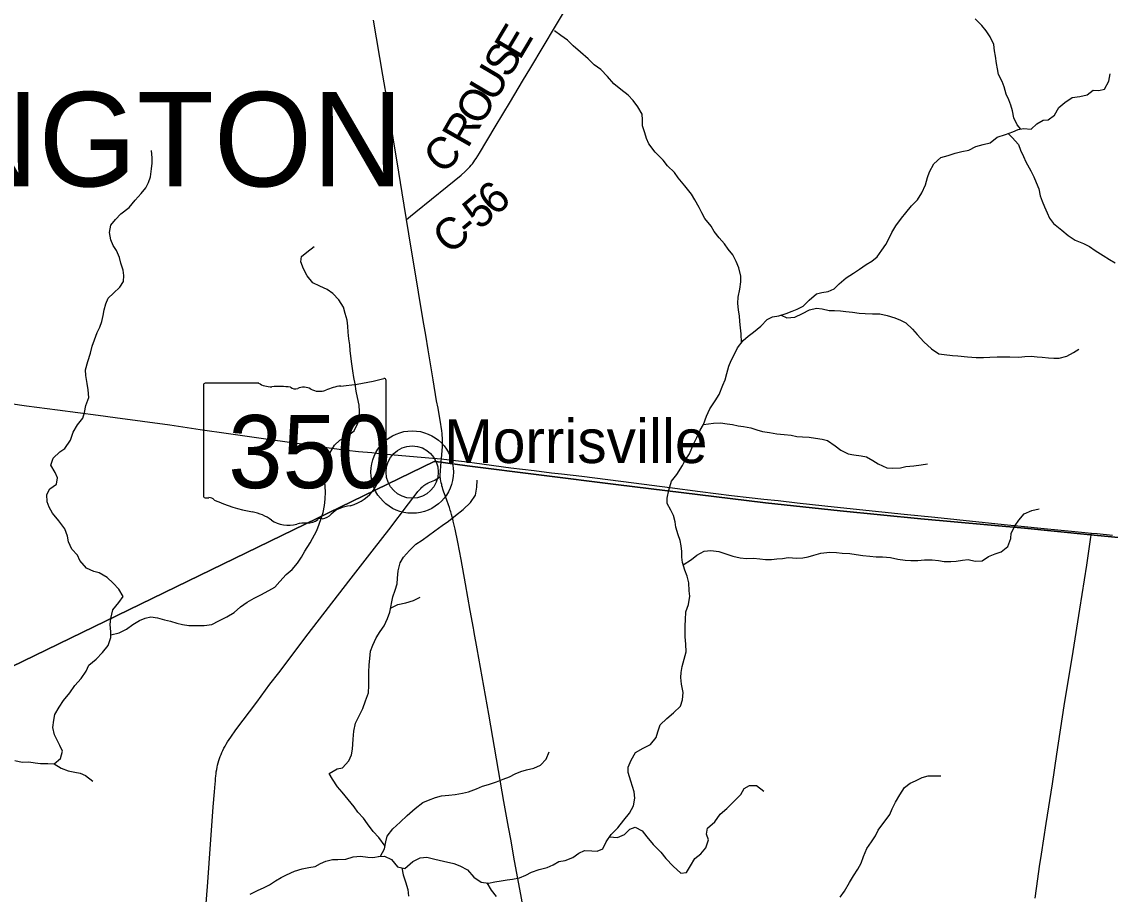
# Model space of a CAD drawing. Extents: x 1442749 to 1756758, y 235267 to 677782.
# Drawn here: x 1596416 to 1606786, y 492250 to 500562 of the extents above; entities that cross this region are included whole.
import ezdxf

# ---------------------------------------------------------------- set-up
doc = ezdxf.new("R2010")
doc.units = 0
for name, color, linetype in [('GM_X_County_Road', 7, 'Continuous'), ('GM_X_County_Road_Text', 7, 'Continuous'), ('GM_X_Minor_River', 7, 'Continuous'), ('GM_X_State_Location', 7, 'Continuous'), ('GM_X_State_Route', 7, 'Continuous'), ('GM_X_State_Shield', 7, 'Continuous'), ('GM_X_Township', 7, 'Continuous'), ('GM_X_Township_Road', 7, 'Continuous'), ('GM_X_Township_Text', 7, 'Continuous'), ('GM_X_Unincorporated', 7, 'Continuous'), ('GM_X_Unincorporated_Location', 7, 'Continuous'), ('GM_X_Unincorporated_Text', 7, 'Continuous')]:
    doc.layers.add(name, color=color, linetype=linetype)

msp = doc.modelspace()

# ---------------------------------------------------------------- linework, layer by layer
at = {"layer": 'GM_X_County_Road'}
for points in [[(1600081, 498678), (1600119, 498709), (1600170, 498750), (1600468, 498992), (1600603, 499102), (1600640, 499134), (1600655, 499149), (1600670, 499163), (1600684, 499179), (1600698, 499195), (1600710, 499210), (1600722, 499226), (1600734, 499242), (1600745, 499258), (1600761, 499284), (1600778, 499310), (1600928, 499560), (1601073, 499803), (1601188, 499997), (1601265, 500127), (1601501, 500521), (1601651, 500772)], [(1598161, 492001), (1598189, 492364), (1598201, 492547), (1598240, 493083), (1598253, 493227), (1598259, 493302), (1598261, 493326), (1598263, 493353), (1598265, 493377), (1598267, 493396), (1598270, 493416), (1598274, 493438), (1598278, 493461), (1598282, 493481), (1598288, 493502), (1598295, 493524), (1598300, 493543), (1598307, 493561), (1598315, 493582), (1598323, 493601), (1598332, 493621), (1598343, 493641), (1598353, 493661), (1598365, 493680), (1598377, 493701), (1598393, 493726), (1598408, 493747), (1598457, 493816), (1598656, 494081), (1598781, 494250), (1598864, 494360), (1599146, 494730), (1599532, 495232), (1599778, 495548), (1599912, 495722), (1600101, 495970), (1600182, 496077), (1600191, 496087), (1600206, 496104), (1600217, 496116), (1600229, 496127), (1600238, 496135), (1600248, 496143), (1600258, 496150), (1600267, 496156), (1600278, 496163), (1600289, 496169), (1600351, 496196), (1600366, 496203), (1600378, 496211), (1600404, 496229)]]:
    msp.add_lwpolyline(points, dxfattribs=at)
at = {"layer": 'GM_X_Minor_River'}
for points in [[(1605936, 499540), (1605900, 499579), (1605869, 499646), (1605856, 499712), (1605839, 499767), (1605821, 499817), (1605796, 499871), (1605775, 499942), (1605756, 499992), (1605722, 500059), (1605711, 500113), (1605704, 500165), (1605693, 500233), (1605685, 500284), (1605676, 500344), (1605643, 500418), (1605604, 500475), (1605562, 500526), (1605499, 500591)], [(1603274, 497506), (1603271, 497589), (1603265, 497645), (1603258, 497708), (1603255, 497760), (1603245, 497814), (1603238, 497882), (1603241, 497938), (1603256, 498014), (1603267, 498084), (1603266, 498138), (1603247, 498217), (1603224, 498279), (1603192, 498342), (1603145, 498394), (1603112, 498447), (1603062, 498502), (1603013, 498564), (1602986, 498615), (1602924, 498688), (1602895, 498742), (1602870, 498793), (1602830, 498864), (1602797, 498918), (1602732, 498999), (1602669, 499074), (1602635, 499127), (1602568, 499190), (1602527, 499242), (1602452, 499319), (1602392, 499398), (1602369, 499449), (1602354, 499503), (1602331, 499571), (1602329, 499628), (1602328, 499680), (1602285, 499752), (1602242, 499811), (1602194, 499862), (1602123, 499915), (1602057, 499970), (1601996, 500041), (1601933, 500106), (1601871, 500153), (1601812, 500210), (1601738, 500273), (1601669, 500332), (1601616, 500386), (1601552, 500431), (1601492, 500476)], [(1603097, 497100), (1603118, 497152), (1603135, 497212), (1603154, 497282), (1603175, 497334), (1603210, 497403), (1603235, 497455), (1603288, 497525), (1603338, 497566), (1603389, 497606), (1603458, 497661), (1603517, 497726), (1603570, 497750), (1603630, 497759), (1603698, 497784), (1603755, 497805), (1603805, 497825), (1603860, 497852), (1603917, 497909), (1603988, 497969), (1604038, 497982), (1604098, 497991), (1604155, 498019), (1604205, 498066), (1604270, 498123), (1604339, 498166), (1604398, 498206), (1604461, 498251), (1604515, 498282), (1604566, 498322), (1604609, 498387), (1604650, 498439), (1604677, 498493), (1604705, 498553), (1604744, 498618), (1604797, 498690), (1604838, 498741), (1604893, 498807), (1604950, 498866), (1604993, 498932), (1605026, 499007), (1605045, 499077), (1605064, 499131), (1605107, 499207), (1605172, 499270), (1605241, 499287), (1605309, 499310), (1605374, 499326), (1605438, 499339), (1605507, 499374), (1605577, 499391), (1605643, 499410), (1605710, 499462), (1605789, 499487), (1605857, 499512), (1605910, 499535), (1605960, 499544), (1606034, 499540), (1606087, 499589), (1606146, 499624), (1606196, 499626), (1606255, 499671), (1606298, 499745), (1606353, 499792), (1606423, 499841), (1606496, 499850), (1606566, 499867), (1606625, 499909), (1606677, 499906), (1606731, 499921), (1606774, 499997), (1606787, 500065)], [(1605813, 499496), (1605853, 499460), (1605912, 499391), (1605931, 499338), (1605961, 499278), (1605982, 499228), (1606029, 499143), (1606058, 499086), (1606082, 499032), (1606105, 498971), (1606118, 498905), (1606137, 498853), (1606159, 498800), (1606186, 498742), (1606207, 498691), (1606247, 498641), (1606324, 498578), (1606384, 498525), (1606451, 498482), (1606533, 498449), (1606589, 498420), (1606644, 498383), (1606718, 498334), (1606778, 498297), (1606833, 498266)], [(1596771, 495807), (1596710, 495880), (1596678, 495937), (1596659, 495989), (1596654, 496059), (1596683, 496111), (1596746, 496158), (1596756, 496218), (1596735, 496269), (1596692, 496338), (1596715, 496405), (1596778, 496465), (1596828, 496496), (1596882, 496576), (1596905, 496653), (1596948, 496723), (1596997, 496787), (1597013, 496838), (1597026, 496906), (1597054, 496982), (1597050, 497054), (1597039, 497115), (1597026, 497191), (1597025, 497245), (1597046, 497325), (1597071, 497405), (1597088, 497471), (1597109, 497533), (1597134, 497601), (1597159, 497654), (1597180, 497706), (1597192, 497764), (1597203, 497818), (1597218, 497874), (1597239, 497930), (1597289, 497975), (1597352, 498035), (1597387, 498088), (1597388, 498146), (1597383, 498197), (1597360, 498261), (1597346, 498315), (1597319, 498382), (1597288, 498432), (1597264, 498485), (1597251, 498555), (1597264, 498623), (1597309, 498679), (1597360, 498732), (1597439, 498793), (1597496, 498861), (1597555, 498926), (1597598, 498979), (1597625, 499031), (1597643, 499083), (1597654, 499161), (1597659, 499215), (1597658, 499265), (1597653, 499334)], [(1597266, 494721), (1597344, 494740), (1597413, 494775), (1597476, 494820), (1597538, 494859), (1597593, 494881), (1597645, 494892), (1597711, 494883), (1597777, 494864), (1597835, 494852), (1597893, 494833), (1597949, 494820), (1598009, 494809), (1598079, 494810), (1598153, 494811), (1598226, 494820), (1598294, 494854), (1598371, 494893), (1598440, 494934), (1598499, 494989), (1598563, 495033), (1598632, 495070), (1598695, 495103), (1598771, 495144), (1598826, 495177), (1598875, 495229), (1598934, 495296), (1598993, 495344), (1599042, 495403), (1599083, 495461), (1599113, 495520), (1599165, 495598), (1599226, 495717), (1599249, 495777), (1599268, 495829), (1599287, 495887), (1599302, 495953), (1599307, 496013), (1599310, 496083), (1599308, 496133), (1599303, 496183), (1599304, 496244), (1599306, 496296), (1599323, 496372), (1599351, 496453), (1599396, 496529), (1599447, 496576), (1599519, 496616), (1599582, 496665), (1599617, 496739), (1599630, 496794), (1599635, 496849), (1599630, 496909), (1599614, 496981), (1599601, 497043), (1599592, 497112), (1599581, 497172), (1599570, 497236), (1599561, 497302), (1599552, 497375), (1599546, 497429), (1599541, 497485), (1599534, 497541), (1599525, 497604), (1599523, 497662), (1599518, 497720), (1599499, 497784), (1599482, 497843), (1599438, 497913), (1599381, 497972), (1599325, 498011), (1599256, 498044), (1599190, 498075), (1599135, 498140), (1599102, 498208), (1599074, 498275), (1599081, 498325), (1599132, 498366), (1599201, 498422)], [(1603651, 497766), (1603706, 497742), (1603780, 497747), (1603853, 497782), (1603921, 497817), (1603988, 497832), (1604042, 497828), (1604108, 497811), (1604160, 497810), (1604218, 497807), (1604268, 497801), (1604330, 497796), (1604396, 497785), (1604452, 497784), (1604521, 497781), (1604591, 497778), (1604661, 497763), (1604733, 497740), (1604788, 497718), (1604840, 497693), (1604904, 497634), (1604947, 497583), (1605012, 497512), (1605084, 497447), (1605155, 497400), (1605205, 497392), (1605283, 497383), (1605333, 497380), (1605427, 497369), (1605508, 497362), (1605578, 497363), (1605638, 497366), (1605708, 497371), (1605831, 497369), (1605915, 497366), (1605973, 497372), (1606033, 497375), (1606089, 497370), (1606139, 497367), (1606197, 497361), (1606250, 497358), (1606300, 497357), (1606372, 497375), (1606435, 497410), (1606487, 497443)], [(1599812, 492609), (1599873, 492612), (1599938, 492581), (1599996, 492513), (1600065, 492496), (1600141, 492561), (1600213, 492596), (1600276, 492605), (1600353, 492586), (1600435, 492567), (1600533, 492544), (1600591, 492521), (1600663, 492484), (1600722, 492413), (1600794, 492366), (1600862, 492357), (1600922, 492370), (1600984, 492378), (1601041, 492387), (1601093, 492394), (1601159, 492407), (1601220, 492433), (1601272, 492460), (1601345, 492485), (1601421, 492504), (1601478, 492531), (1601534, 492563), (1601595, 492572), (1601665, 492601), (1601724, 492643), (1601778, 492666), (1601847, 492665), (1601897, 492662), (1601953, 492682), (1601984, 492751), (1602033, 492819), (1602094, 492882), (1602151, 492956), (1602206, 493023), (1602245, 493093), (1602258, 493167), (1602251, 493227), (1602220, 493328), (1602194, 493410), (1602194, 493462), (1602221, 493528), (1602262, 493600), (1602335, 493641), (1602406, 493678), (1602459, 493745), (1602477, 493799), (1602498, 493865), (1602561, 493924), (1602626, 493980), (1602691, 494043), (1602712, 494101), (1602719, 494171), (1602702, 494251), (1602695, 494314), (1602700, 494364), (1602708, 494420), (1602727, 494491), (1602746, 494561), (1602743, 494634), (1602738, 494704), (1602736, 494812), (1602741, 494866), (1602742, 494940), (1602769, 495010), (1602780, 495090), (1602776, 495142), (1602773, 495216), (1602756, 495281), (1602735, 495337), (1602710, 495412), (1602704, 495462), (1602705, 495514), (1602698, 495568), (1602689, 495620), (1602669, 495673), (1602648, 495747), (1602641, 495797), (1602624, 495858), (1602600, 495908), (1602565, 495973), (1602566, 496023), (1602581, 496101), (1602606, 496185), (1602657, 496250), (1602710, 496334), (1602737, 496385), (1602778, 496447), (1602817, 496537), (1602848, 496602), (1602881, 496672), (1602910, 496724), (1602941, 496804), (1602972, 496875), (1603021, 496951), (1603060, 497011), (1603097, 497100)], [(1602910, 496724), (1603006, 496737), (1603073, 496740), (1603137, 496733), (1603187, 496724), (1603243, 496714), (1603293, 496707), (1603361, 496692), (1603421, 496673), (1603475, 496660), (1603539, 496650), (1603609, 496637), (1603681, 496630), (1603745, 496623), (1603801, 496612), (1603853, 496607), (1603917, 496605), (1603977, 496596), (1604041, 496587), (1604093, 496574), (1604167, 496521), (1604220, 496480), (1604290, 496447), (1604344, 496435), (1604412, 496428), (1604464, 496417), (1604524, 496382), (1604575, 496350), (1604657, 496314), (1604709, 496308), (1604788, 496313), (1604840, 496326), (1604914, 496333), (1604984, 496342), (1605047, 496351)], [(1599878, 492709), (1599817, 492790), (1599765, 492848), (1599710, 492921), (1599671, 492974), (1599617, 493033), (1599584, 493083), (1599527, 493152), (1599470, 493223), (1599426, 493274), (1599377, 493348), (1599346, 493399), (1599420, 493446), (1599473, 493455), (1599534, 493521), (1599559, 493577), (1599567, 493633), (1599573, 493727), (1599580, 493803), (1599597, 493879), (1599634, 493956), (1599665, 494020), (1599692, 494094), (1599719, 494170), (1599724, 494238), (1599723, 494292), (1599722, 494366), (1599727, 494436), (1599731, 494496), (1599740, 494566), (1599761, 494622), (1599794, 494692), (1599831, 494754), (1599868, 494807), (1599901, 494877), (1599922, 494937), (1599952, 495085), (1599973, 495147), (1599992, 495206), (1599996, 495260), (1600001, 495331), (1600022, 495406), (1600053, 495460), (1600110, 495526), (1600171, 495585), (1600230, 495624), (1600293, 495668), (1600351, 495711), (1600422, 495762), (1600483, 495805), (1600550, 495859), (1600621, 495914), (1600690, 495983), (1600739, 496053), (1600752, 496129), (1600755, 496195)], [(1602718, 495387), (1602798, 495439), (1602849, 495480), (1602918, 495517), (1602982, 495526), (1603058, 495515), (1603114, 495495), (1603190, 495470), (1603262, 495455), (1603320, 495450), (1603388, 495451), (1603448, 495444), (1603502, 495439), (1603558, 495439), (1603611, 495446), (1603663, 495449), (1603719, 495459), (1603801, 495452), (1603857, 495455), (1603908, 495464), (1603964, 495482), (1604029, 495499), (1604115, 495508), (1604179, 495505), (1604233, 495498), (1604305, 495495), (1604365, 495486), (1604429, 495478), (1604497, 495471), (1604556, 495466), (1604618, 495465), (1604694, 495458), (1604762, 495443), (1604834, 495434), (1604888, 495430), (1604954, 495431), (1605018, 495436), (1605091, 495435), (1605151, 495430), (1605205, 495421), (1605267, 495419), (1605319, 495424), (1605379, 495433), (1605434, 495438), (1605500, 495422), (1605566, 495427), (1605628, 495468), (1605691, 495493), (1605747, 495511), (1605812, 495564), (1605839, 495638), (1605842, 495690), (1605881, 495763), (1605916, 495815), (1605967, 495873), (1606039, 495906), (1606110, 495921)], [(1596351, 493524), (1596421, 493509), (1596483, 493512), (1596543, 493503), (1596595, 493495), (1596666, 493496), (1596726, 493493), (1596787, 493544), (1596804, 493612), (1596780, 493667), (1596755, 493717), (1596728, 493770), (1596712, 493840), (1596721, 493910), (1596732, 493964), (1596773, 494034), (1596814, 494097), (1596873, 494169), (1596922, 494238), (1596981, 494307), (1597030, 494377), (1597057, 494431), (1597124, 494490), (1597187, 494553), (1597240, 494619), (1597265, 494695), (1597266, 494751), (1597259, 494821), (1597266, 494877), (1597285, 494959), (1597342, 495028), (1597381, 495086), (1597340, 495157), (1597288, 495213), (1597229, 495268), (1597155, 495313), (1597103, 495326), (1597032, 495357), (1596970, 495430), (1596947, 495482), (1596892, 495539), (1596863, 495606), (1596853, 495660), (1596826, 495732), (1596771, 495807)], [(1599930, 494977), (1599999, 495010), (1600077, 495025), (1600150, 495048), (1600211, 495081)], [(1599427, 492580), (1599505, 492585), (1599574, 492606), (1599644, 492613), (1599712, 492602), (1599762, 492600), (1599834, 492613), (1599873, 492683), (1599884, 492751), (1599899, 492802), (1599952, 492872), (1600023, 492937), (1600088, 493002), (1600163, 493066), (1600238, 493123), (1600293, 493148), (1600359, 493173), (1600416, 493187), (1600484, 493194), (1600544, 493201), (1600615, 493212), (1600673, 493227), (1600748, 493256), (1600806, 493280), (1600864, 493295), (1600939, 493320), (1601003, 493345), (1601062, 493369), (1601116, 493396), (1601171, 493419), (1601225, 493435), (1601296, 493452), (1601360, 493479), (1601413, 493538), (1601442, 493606)], [(1596726, 493493), (1596793, 493452), (1596859, 493427), (1596921, 493414), (1596973, 493404), (1597025, 493383), (1597093, 493328)], [(1604213, 492221), (1604254, 492279), (1604301, 492363), (1604342, 492426), (1604383, 492488), (1604414, 492546), (1604435, 492609), (1604468, 492685), (1604511, 492751), (1604550, 492806), (1604577, 492862), (1604687, 493009), (1604710, 493065), (1604741, 493129), (1604782, 493196), (1604825, 493266), (1604879, 493307), (1604930, 493330), (1604996, 493362), (1605053, 493377), (1605123, 493378), (1605173, 493377)], [(1602017, 492797), (1602091, 492790), (1602159, 492819), (1602210, 492869), (1602261, 492888), (1602328, 492855), (1602372, 492796), (1602433, 492724), (1602504, 492652), (1602552, 492592), (1602623, 492517), (1602696, 492452), (1602748, 492459), (1602787, 492520), (1602830, 492592), (1602885, 492635), (1602934, 492693), (1602959, 492769), (1602940, 492823), (1602948, 492879), (1603019, 492940), (1603071, 493012), (1603135, 493067), (1603192, 493125), (1603266, 493200), (1603300, 493257), (1603351, 493287), (1603417, 493286), (1603487, 493231)], [(1598594, 492250), (1598661, 492287), (1598727, 492315), (1598778, 492340), (1598835, 492379), (1598889, 492411), (1598940, 492436), (1599016, 492471), (1599087, 492492), (1599151, 492504), (1599211, 492515), (1599264, 492542), (1599314, 492566), (1599377, 492581), (1599427, 492580)], [(1600037, 492503), (1600051, 492434), (1600072, 492369), (1600093, 492297), (1600102, 492231)], [(1600848, 492359), (1600889, 492289), (1600936, 492228)]]:
    msp.add_lwpolyline(points, dxfattribs=at)
at = {"layer": 'GM_X_State_Route'}
for points in [[(1601078, 492760), (1601054, 492889), (1601010, 493135), (1600957, 493428), (1600865, 493965), (1600755, 494588), (1600728, 494744), (1600724, 494766), (1600721, 494784), (1600689, 494953), (1600645, 495208), (1600604, 495438), (1600571, 495605), (1600545, 495727), (1600526, 495805), (1600522, 495826), (1600516, 495846), (1600511, 495867), (1600503, 495893), (1600497, 495910), (1600490, 495933), (1600481, 495960), (1600449, 496050), (1600438, 496082), (1600429, 496109), (1600424, 496125), (1600420, 496140), (1600417, 496153), (1600413, 496171), (1600409, 496189), (1600407, 496201), (1600405, 496212), (1600404, 496229), (1600404, 496238), (1600404, 496255), (1600405, 496272), (1600406, 496293), (1600408, 496318), (1600412, 496378), (1600414, 496398), (1600425, 496515), (1600426, 496538), (1600426, 496558), (1600425, 496579), (1600425, 496597), (1600423, 496620), (1600421, 496639), (1600417, 496664), (1600414, 496686), (1600412, 496704), (1600408, 496728), (1600402, 496762), (1600382, 496881), (1600369, 496952), (1600337, 497150), (1600320, 497247), (1600288, 497438), (1600265, 497577), (1600242, 497716), (1600197, 497985), (1600105, 498541), (1600081, 498678), (1600078, 498696), (1600040, 498933), (1600008, 499130), (1599955, 499457), (1599903, 499781), (1599856, 500053), (1599768, 500577)], [(1596155, 496946), (1596460, 496904), (1596757, 496866), (1597143, 496813), (1597306, 496792), (1597826, 496721), (1598115, 496679), (1598385, 496641), (1598654, 496602), (1598787, 496583), (1599125, 496535), (1599346, 496503), (1599512, 496481), (1599626, 496468), (1599750, 496457), (1599848, 496447), (1599930, 496441), (1600109, 496425), (1600332, 496406), (1600414, 496398)], [(1600414, 496398), (1600439, 496396), (1600634, 496372), (1600729, 496359), (1601077, 496314), (1601298, 496287), (1601464, 496266), (1601559, 496255), (1601751, 496232), (1602248, 496168), (1602590, 496124), (1602879, 496086), (1603179, 496049), (1603345, 496030), (1603485, 496014), (1603622, 496000), (1603805, 495980), (1604066, 495951), (1604398, 495915), (1604822, 495871), (1605116, 495841), (1605325, 495819), (1605775, 495773), (1605971, 495755), (1606157, 495735), (1606418, 495709), (1606607, 495691), (1606663, 495686), (1606807, 495671)], [(1601254, 491783), (1601247, 491824), (1601177, 492212), (1601106, 492602), (1601078, 492760)]]:
    msp.add_lwpolyline(points, dxfattribs=at)
at = {"layer": 'GM_X_State_Shield'}
for p, q in [((1599887, 496593), (1599887, 497146)), ((1598147, 497101), (1598147, 496045)), ((1598674, 497119), (1598164, 497119)), ((1599887, 496593), (1599887, 496593))]:
    msp.add_line(p, q, dxfattribs=at)
for centre, major_axis, start_param, end_param in [((1599268, 498560), (1845, 0), 4.814394, 5.042369), ((1599868, 497148), (19.4, 0), 6.141152, 7.989035), ((1598167, 497103), (20.2, 0), 1.712693, 3.28349), ((1598795, 497242), (196, 0), 4.042523, 4.731795), ((1598860, 496526), (702, 0), 1.404758, 1.657858), ((1599020, 497109), (56.4, 0), 3.836095, 5.185415), ((1599102, 496987), (117, 0), 0.950623, 2.079405), ((1599254, 497154), (141, 0), 4.081561, 5.145723), ((1599503, 496797), (371, 0), 1.699011, 2.107814), ((1599883, 496552), (30, 0), 1.883978, 3.671073), ((1599692, 496482), (180, 0), 5.934695, 6.695948), ((1599867, 496591), (20.7, 0), 5.05454, 6.418171), ((1599957, 496362), (131, 0), 2.387724, 3.262537), ((1599371, 496291), (462, 0), 5.101752, 6.440018), ((1598167, 496042), (20.3, 0), 3.00124, 4.508301), ((1598170, 496150), (155, 0), 4.665946, 4.897461), ((1598202, 495984), (56, 0), 0.519207, 1.627899), ((1598909, 496933), (1333, 0), 4.195997, 4.488961), ((1598511, 495570), (417, 0), 0.823519, 1.323587), ((1599566, 495748), (253, 0), 1.647645, 2.488434), ((1598962, 495978), (265, 0), 4.026481, 4.996735), ((1599115, 495613), (217, 0), 1.495662, 1.94098), ((1599135, 495899), (141, 0), 4.691044, 5.507374), ((1599262, 495797), (39.7, 0), 1.147584, 2.315152), ((1599245, 495942), (149, 0), 4.937069, 5.64225)]:
    msp.add_ellipse(centre, major_axis=major_axis, ratio=0.8, start_param=start_param, end_param=end_param, dxfattribs=at)
at = {"layer": 'GM_X_Township'}
for points in [[(1594192, 493386), (1600346, 496373), (1600362, 496372), (1600659, 496333), (1602075, 496153), (1603501, 495979), (1604214, 495902), (1604981, 495826), (1605969, 495737), (1606568, 495678), (1607792, 495559), (1608831, 495454), (1609316, 495410), (1609370, 495408), (1609456, 495411), (1609779, 495455), (1610206, 495544), (1610388, 495579), (1610664, 495613), (1612170, 495715), (1612399, 495724), (1612561, 495727), (1612809, 495716), (1614072, 489613)], [(1607792, 495559), (1606568, 495678), (1605969, 495737), (1604981, 495826), (1604214, 495902), (1603501, 495979), (1602075, 496153), (1600659, 496333), (1600362, 496372), (1600346, 496373), (1594192, 493386)]]:
    msp.add_lwpolyline(points, dxfattribs=at)
at = {"layer": 'GM_X_Township_Road'}
msp.add_lwpolyline([(1606070, 492214), (1606098, 492398), (1606114, 492515), (1606132, 492632), (1606176, 492923), (1606235, 493303), (1606278, 493585), (1606349, 494045), (1606434, 494563), (1606496, 494965), (1606562, 495386), (1606592, 495584), (1606602, 495653), (1606607, 495691)], dxfattribs=at)
at = {"layer": 'GM_X_Unincorporated'}
for radius in [393, 249]:
    msp.add_circle((1600136, 496272), radius, dxfattribs=at)
at = {"layer": 'GM_X_Unincorporated_Location'}
msp.add_line((1600136, 496272), (1600136, 496272), dxfattribs=at)

# ---------------------------------------------------------------- texts
at = {"layer": 'GM_X_County_Road_Text'}
for s, rotation, p in [('E', 59.278, (1601161, 500187)), ('S', 59.2815, (1601057, 500013)), ('U', 59.2808, (1600922, 499786)), ('O', 59.2786, (1600788, 499559)), ('R', 60.2818, (1600666, 499347)), ('C', 41.1195, (1600411, 499100)), ('6', 42.7161, (1600930, 498701)), ('5', 39.7866, (1600776, 498572)), ('C', 39.4772, (1600489, 498336)), ('-', 39.5417, (1600680, 498493))]:
    msp.add_text(s, height=300, rotation=rotation, dxfattribs=at).set_placement(p)
at = {"layer": 'GM_X_State_Location'}
msp.add_text('350', height=1, rotation=0, dxfattribs=at).set_placement((1598645, 496430))
for s in ['s', 'r']:
    msp.add_text(s, height=1, dxfattribs=at).set_placement((1598998, 496503))
at = {"layer": 'GM_X_State_Shield'}
msp.add_text('350', height=696.1, dxfattribs=at).set_placement((1598383, 496119))
at = {"layer": 'GM_X_Township_Text'}
msp.add_text('WASHINGTON', height=900, rotation=0, dxfattribs=at).set_placement((1591762, 498993))
at = {"layer": 'GM_X_Unincorporated_Text'}
msp.add_text('Morrisville', height=417, rotation=0, dxfattribs=at).set_placement((1600440, 496358))

doc.saveas('drawing.dxf')
